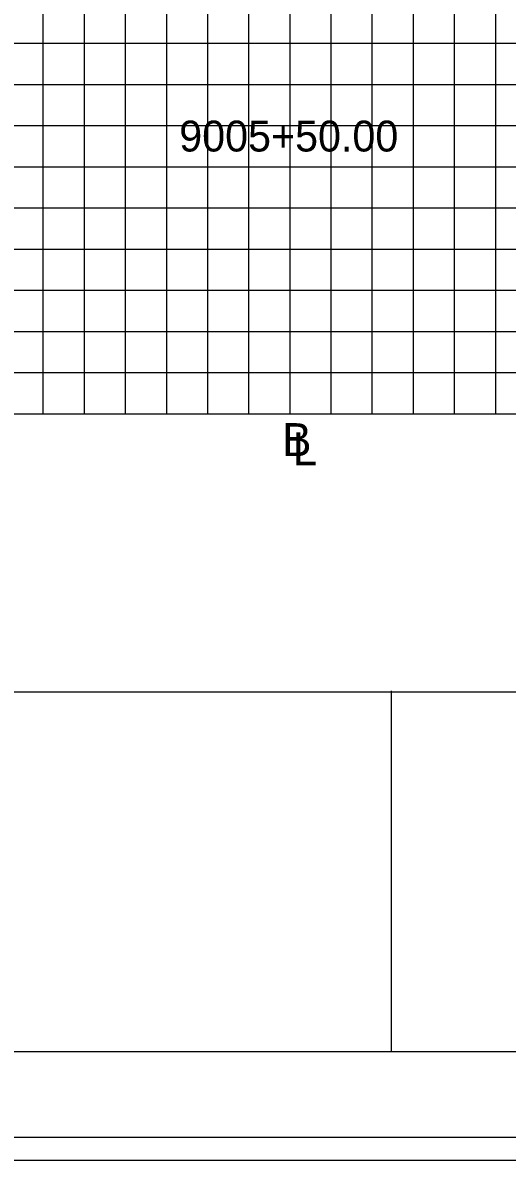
# Model space of a CAD drawing. Extents: x 967 to 1326, y 964 to 2584.
# Drawn here: x 1147 to 1170.6, y 1523.7 to 1579 of the extents above; entities that cross this region are included whole.
import ezdxf

# ---------------------------------------------------------------- set-up
doc = ezdxf.new("R2010")
doc.units = 0
for name, color, linetype in [('Default', 7, 'Continuous'), ('RD_GPK_XS_Cell', 7, 'Continuous'), ('RD_XS_ExGround', 7, 'Continuous'), ('RD_XS_ExPaveRet', 7, 'Continuous'), ('RD_XS_Misc_Line', 7, 'Continuous'), ('RD_XS_TX_Elev_EX', 7, 'Continuous')]:
    doc.layers.add(name, color=color, linetype=linetype)

msp = doc.modelspace()

# ---------------------------------------------------------------- linework, layer by layer
at = {"layer": 'RD_GPK_XS_Cell'}
for p, q in [((1150, 1560), (1150, 1730)), ((1160, 1560), (1160, 1730)), ((1170, 1560), (1170, 1730)), ((1000, 1570), (1320, 1570)), ((1000, 1560), (1320, 1560))]:
    msp.add_line(p, q, dxfattribs=at)
at = {"layer": 'RD_XS_ExGround'}
for p, q in [((1148, 1560), (1148, 1730)), ((1152, 1560), (1152, 1730)), ((1154, 1560), (1154, 1730)), ((1156, 1560), (1156, 1730)), ((1158, 1560), (1158, 1730)), ((1162, 1560), (1162, 1730)), ((1164, 1560), (1164, 1730)), ((1166, 1560), (1166, 1730)), ((1168, 1560), (1168, 1730)), ((1000, 1578), (1320, 1578)), ((1000, 1576), (1320, 1576)), ((1000, 1574), (1320, 1574)), ((1000, 1572), (1320, 1572)), ((1000, 1568), (1320, 1568)), ((1000, 1566), (1320, 1566)), ((1000, 1564), (1320, 1564)), ((1000, 1562), (1320, 1562))]:
    msp.add_line(p, q, dxfattribs=at)
at = {"layer": 'RD_XS_ExPaveRet'}
for points in [[(967.409, 1523.72), (1326.285, 1523.72), (1326.285, 1743.72), (967.409, 1743.72)], [(988.525, 1524.84), (1326.285, 1524.84), (1326.285, 1742.6), (988.525, 1742.6)]]:
    msp.add_lwpolyline(points, close=True, dxfattribs=at)
at = {"layer": 'RD_XS_TX_Elev_EX'}
for p, q in [((996.114, 1546.486), (1323.886, 1546.486)), ((1164.932, 1528.983), (1164.932, 1546.526)), ((1323.886, 1528.983), (996.114, 1528.983))]:
    msp.add_line(p, q, dxfattribs=at)

# ---------------------------------------------------------------- texts
at = {"layer": 'Default'}
msp.add_text('9005+50.00', height=1.5, dxfattribs=at).set_placement((1154.611, 1572.743))
at = {"layer": 'RD_XS_Misc_Line'}
for s, p in [('B', (1159.615, 1557.941)), ('L', (1160.124, 1557.491))]:
    msp.add_text(s, height=1.6, dxfattribs=at).set_placement(p)

doc.saveas('drawing.dxf')
